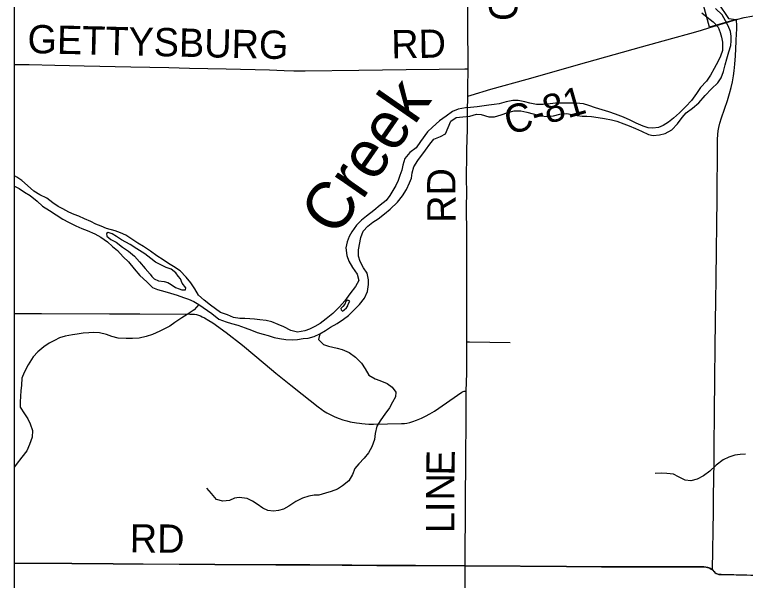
# Model space of a CAD drawing. Extents: x -87 to 2145, y -2128 to 440.
# Drawn here: x -21.62 to 17.09, y -1230.38 to -1200.4 of the extents above; entities that cross this region are included whole.
import ezdxf

# ---------------------------------------------------------------- set-up
doc = ezdxf.new("R2010")
doc.units = 0
for name, color, linetype in [('GM_X_Corporation', 7, 'Continuous'), ('GM_X_County_Road', 7, 'Continuous'), ('GM_X_County_Road_Text', 7, 'Continuous'), ('GM_X_Major_River', 7, 'Continuous'), ('GM_X_Major_River_Text', 7, 'Continuous'), ('GM_X_Minor_River', 7, 'Continuous'), ('GM_X_Township_Road', 7, 'Continuous'), ('GM_X_Township_Text', 7, 'Continuous'), ('SC_Scratch1', 7, 'Continuous')]:
    doc.layers.add(name, color=color, linetype=linetype)

msp = doc.modelspace()

# ---------------------------------------------------------------- linework, layer by layer
at = {"layer": 'GM_X_Corporation'}
msp.add_lwpolyline([(15.645, -1199.79), (16.19, -1200.598), (16.606, -1200.653), (15.194, -1201.071), (14.872, -1199.892)], dxfattribs=at)
at = {"layer": 'GM_X_County_Road'}
for points in [[(2.402, -1203.264), (2.402, -1203.242), (2.394, -1200.852), (2.388, -1199.683), (2.389, -1199.192), (2.393, -1198.818), (2.44, -1195.798), (2.472, -1192.879), (2.491, -1191.436), (2.497, -1190.304), (2.501, -1189.435), (2.507, -1188.271), (2.508, -1187.188), (2.497, -1185.974), (2.508, -1185.389)], [(15.2, -1201.085), (16.439, -1200.718), (16.612, -1200.667)], [(16.612, -1200.667), (17.033, -1200.553), (17.432, -1200.479), (18.193, -1200.365)], [(2.388, -1204.721), (2.564, -1204.668), (3.615, -1204.351), (5.525, -1203.815), (8.699, -1202.926), (11.586, -1202.107), (13.245, -1201.648), (14.144, -1201.396), (14.706, -1201.233), (15.2, -1201.085)], [(-21.617, -1203.042), (-20.84, -1203.048), (-19.479, -1203.078), (-17.937, -1203.113), (-15.461, -1203.173), (-13.444, -1203.208), (-12.361, -1203.229), (-10.409, -1203.267), (-8.114, -1203.327), (-7.344, -1203.353), (-6.82, -1203.373), (-6.229, -1203.382), (-3.392, -1203.337), (-0.882, -1203.316), (0.872, -1203.286), (2.233, -1203.266), (2.402, -1203.264)], [(2.388, -1204.721), (2.393, -1204.291), (2.402, -1203.264)], [(2.329, -1217.741), (2.332, -1215.445), (2.333, -1212.279), (2.325, -1210.355), (2.331, -1210.059), (2.325, -1208.847), (2.336, -1208.016), (2.342, -1207.571), (2.365, -1206.472), (2.378, -1205.52), (2.388, -1204.721)], [(2.308, -1220.351), (2.33, -1219.4), (2.329, -1217.741)], [(2.247, -1229.607), (2.267, -1226.169), (2.276, -1223.987), (2.303, -1221.806), (2.308, -1220.351)], [(-21.617, -1229.469), (-18.589, -1229.488), (-16.391, -1229.504), (-14.816, -1229.513), (-11.011, -1229.542), (-9.175, -1229.55), (-7.78, -1229.562), (-6.911, -1229.562), (-5.976, -1229.561), (-4.271, -1229.573), (-3.746, -1229.58), (-2.435, -1229.587), (-0.384, -1229.59), (2.247, -1229.607)], [(2.151, -1245.188), (2.161, -1243.21), (2.168, -1242.522), (2.182, -1240.75), (2.184, -1239.913), (2.187, -1239.274), (2.188, -1238.568), (2.189, -1237.716), (2.205, -1235.764), (2.219, -1233.549), (2.226, -1232.089), (2.241, -1230.4), (2.247, -1229.607)]]:
    msp.add_lwpolyline(points, dxfattribs=at)
at = {"layer": 'GM_X_Major_River'}
for points in [[(0.141, -1207.591), (0.377, -1207.274), (0.582, -1206.997), (0.935, -1206.853), (1.198, -1206.717), (1.354, -1206.389), (1.49, -1206.05), (1.774, -1205.855), (2.125, -1205.821), (2.486, -1205.776), (2.849, -1205.672), (3.099, -1205.687), (3.498, -1205.814), (3.809, -1205.819), (4.151, -1205.714), (4.514, -1205.58), (4.836, -1205.505), (5.187, -1205.501), (5.517, -1205.567), (5.856, -1205.663), (6.245, -1205.77), (6.605, -1205.806), (6.927, -1205.771), (7.259, -1205.676), (7.63, -1205.643), (8.06, -1205.73), (8.44, -1205.777), (8.691, -1205.781), (8.941, -1205.805), (9.291, -1205.851), (9.631, -1205.907), (9.99, -1205.983), (10.28, -1206.048), (10.648, -1206.185), (10.927, -1206.299), (11.266, -1206.435), (11.594, -1206.581), (11.952, -1206.758), (12.211, -1206.812), (12.543, -1206.778), (12.845, -1206.693), (13.189, -1206.498), (13.495, -1206.192), (13.741, -1205.856), (13.956, -1205.599), (14.28, -1205.364), (14.626, -1205.079), (14.963, -1204.684), (15.29, -1204.328), (15.626, -1204.013), (15.801, -1203.756), (15.936, -1203.417), (16.023, -1203.058), (16.108, -1202.749), (16.214, -1202.38), (16.31, -1202.041), (16.334, -1201.79), (16.339, -1201.54), (16.293, -1201.289), (16.177, -1200.986), (16.031, -1200.733), (15.856, -1200.419), (15.511, -1200.083)], [(14.786, -1200.301), (15.062, -1200.526), (15.379, -1200.782)], [(15.379, -1200.782), (15.655, -1201.067), (15.761, -1201.34), (15.817, -1201.591), (15.882, -1201.863), (15.885, -1202.294), (15.78, -1202.593), (15.655, -1202.871), (15.428, -1203.258), (15.242, -1203.606), (15.036, -1203.923), (14.72, -1204.259), (14.494, -1204.586), (14.227, -1204.952), (13.941, -1205.268), (13.605, -1205.603), (13.279, -1205.888), (13.025, -1206.104), (12.742, -1206.27), (12.489, -1206.386), (12.188, -1206.421), (11.938, -1206.397), (11.679, -1206.312), (11.311, -1206.146), (10.992, -1206), (10.634, -1205.833), (10.216, -1205.676), (9.857, -1205.55), (9.498, -1205.444), (9.159, -1205.338), (8.79, -1205.211), (8.511, -1205.136), (8.131, -1205.09), (7.79, -1205.084), (7.449, -1205.088), (7.028, -1205.101), (6.757, -1205.127), (6.376, -1205.16), (6.025, -1205.165), (5.665, -1205.088), (5.406, -1205.024), (5.046, -1204.958), (4.765, -1204.953), (4.423, -1205.027), (4.041, -1205.121), (3.79, -1205.157), (3.508, -1205.192), (3.127, -1205.256), (2.875, -1205.292), (2.534, -1205.326), (2.263, -1205.342), (1.881, -1205.416), (1.568, -1205.541), (1.234, -1205.775), (0.889, -1206.03), (0.512, -1206.365), (0.247, -1206.611)], [(0.247, -1206.611), (-0.122, -1207.128), (-0.349, -1207.454), (-0.684, -1207.708), (-0.951, -1208.023), (-1.048, -1208.381), (-1.113, -1208.65), (-1.208, -1208.918), (-1.294, -1209.197), (-1.429, -1209.464), (-1.584, -1209.721), (-1.749, -1209.978), (-1.935, -1210.245), (-2.26, -1210.499), (-2.586, -1210.782), (-2.982, -1211.085), (-3.237, -1211.29), (-3.502, -1211.565), (-3.759, -1211.91), (-3.904, -1212.167), (-4.01, -1212.446), (-4.076, -1212.764), (-4.024, -1213.166), (-3.919, -1213.458), (-3.725, -1213.802), (-3.482, -1214.157), (-3.388, -1214.489), (-3.565, -1214.816), (-3.863, -1215.2), (-4.13, -1215.565), (-4.407, -1215.89), (-4.754, -1216.244), (-5.11, -1216.517), (-5.425, -1216.771), (-5.708, -1216.925), (-5.991, -1217.07), (-6.253, -1217.155), (-6.625, -1217.227), (-6.984, -1217.14), (-7.351, -1216.943), (-7.659, -1216.827), (-7.997, -1216.69), (-8.295, -1216.604), (-8.635, -1216.568), (-8.905, -1216.542), (-9.165, -1216.517), (-9.415, -1216.512), (-9.695, -1216.497), (-10.015, -1216.46), (-10.342, -1216.314), (-10.71, -1216.186), (-10.977, -1215.991), (-11.234, -1215.806), (-11.579, -1215.539), (-11.884, -1215.263), (-12.068, -1214.939), (-12.282, -1214.615), (-12.527, -1214.31), (-12.851, -1213.983), (-13.197, -1213.746), (-13.464, -1213.591), (-13.741, -1213.395), (-14.077, -1213.178), (-14.412, -1212.932), (-14.798, -1212.684), (-15.095, -1212.518), (-15.352, -1212.343), (-15.728, -1212.085), (-16.016, -1211.97), (-16.284, -1211.864), (-16.742, -1211.735), (-17.04, -1211.609), (-17.309, -1211.504), (-17.586, -1211.358), (-17.914, -1211.222), (-18.212, -1211.086), (-18.47, -1210.991), (-18.739, -1210.875), (-19.056, -1210.699), (-19.313, -1210.564), (-19.59, -1210.368), (-19.916, -1210.132), (-20.273, -1209.945), (-20.599, -1209.748), (-20.934, -1209.451), (-21.239, -1209.195), (-21.496, -1209.02), (-21.617, -1208.945)], [(-21.617, -1209.487), (-21.378, -1209.623), (-21.101, -1209.808), (-20.794, -1209.985), (-20.419, -1210.292), (-20.134, -1210.548), (-19.768, -1210.775), (-19.422, -1211.002), (-19.066, -1211.239), (-18.769, -1211.395), (-18.382, -1211.593), (-18.054, -1211.739), (-17.776, -1211.835), (-17.369, -1212.023), (-17.052, -1212.199), (-16.706, -1212.436), (-16.44, -1212.682), (-16.174, -1212.907), (-15.87, -1213.233), (-15.585, -1213.509), (-15.292, -1213.875), (-14.978, -1214.221), (-14.614, -1214.569), (-14.32, -1214.865), (-14.041, -1214.97), (-13.663, -1215.078), (-13.354, -1215.164), (-13.006, -1215.271), (-12.668, -1215.398), (-12.399, -1215.483), (-12.121, -1215.608), (-11.863, -1215.754), (-11.172, -1216.248), (-10.807, -1216.535), (-10.409, -1216.673), (-10.121, -1216.768), (-9.802, -1216.865), (-9.404, -1216.993), (-9.076, -1217.129), (-8.778, -1217.245), (-8.46, -1217.341), (-8.19, -1217.397), (-7.862, -1217.503), (-7.593, -1217.569), (-7.244, -1217.626), (-6.903, -1217.642), (-6.633, -1217.618), (-6.331, -1217.573), (-6.071, -1217.549), (-5.758, -1217.455), (-5.445, -1217.321), (-5.142, -1217.147), (-4.888, -1216.971), (-4.534, -1216.768), (-4.189, -1216.545), (-3.935, -1216.34), (-3.68, -1216.105), (-3.343, -1215.761), (-3.086, -1215.426), (-2.919, -1215.079), (-2.872, -1214.709), (-2.867, -1214.459), (-2.95, -1214.097), (-3.135, -1213.814), (-3.319, -1213.48), (-3.404, -1213.208), (-3.397, -1212.868), (-3.284, -1212.21), (-3.158, -1211.882), (-2.912, -1211.607), (-2.638, -1211.402), (-2.354, -1211.217), (-2.029, -1210.963), (-1.723, -1210.709), (-1.336, -1210.337), (-1.069, -1210.012), (-0.852, -1209.676), (-0.705, -1209.318), (-0.6, -1209.06), (-0.565, -1208.781), (-0.479, -1208.472), (-0.252, -1208.136), (0.141, -1207.591)], [(-14.153, -1213.517), (-14.41, -1213.332), (-14.726, -1213.076), (-15.141, -1212.817), (-15.497, -1212.58), (-15.953, -1212.331), (-16.22, -1212.156), (-16.458, -1212.021), (-16.666, -1211.947), (-16.747, -1211.995), (-16.73, -1212.146), (-16.523, -1212.32), (-16.246, -1212.465), (-15.91, -1212.722), (-15.584, -1212.929), (-15.259, -1213.205), (-14.994, -1213.501), (-14.71, -1213.846), (-14.446, -1214.152), (-14.358, -1214.274)], [(-14.358, -1214.274), (-14.231, -1214.406), (-13.992, -1214.501), (-13.703, -1214.547), (-13.503, -1214.601), (-13.325, -1214.704), (-13.088, -1214.859), (-12.899, -1214.933), (-12.76, -1214.985), (-12.57, -1214.989), (-12.548, -1214.88), (-12.743, -1214.636), (-12.839, -1214.404), (-12.946, -1214.261), (-13.073, -1214.079), (-13.33, -1213.894), (-13.588, -1213.808), (-14.153, -1213.517)], [(-3.86, -1215.581), (-3.959, -1215.529), (-4.071, -1215.607), (-4.133, -1215.745), (-4.226, -1215.864), (-4.338, -1215.971), (-4.329, -1216.042), (-4.251, -1216.113)], [(-4.251, -1216.113), (-4.159, -1216.045), (-4.047, -1215.937), (-3.975, -1215.829), (-3.943, -1215.749), (-3.86, -1215.581)]]:
    msp.add_lwpolyline(points, dxfattribs=at)
at = {"layer": 'GM_X_Minor_River'}
for points in [[(-11.863, -1215.754), (-12.099, -1216.039), (-12.485, -1216.292), (-12.768, -1216.466), (-13.124, -1216.709), (-13.398, -1216.904), (-13.651, -1217.039), (-13.923, -1217.174), (-14.317, -1217.346), (-14.65, -1217.46), (-15.022, -1217.543), (-15.373, -1217.566), (-15.713, -1217.569), (-16.134, -1217.551), (-16.462, -1217.454), (-16.75, -1217.349), (-17.129, -1217.261), (-17.44, -1217.255), (-17.69, -1217.26), (-17.981, -1217.285), (-18.302, -1217.338), (-18.553, -1217.363), (-18.935, -1217.436), (-19.247, -1217.53), (-19.51, -1217.675), (-19.793, -1217.819), (-20.077, -1218.004), (-20.393, -1218.278), (-20.638, -1218.533), (-20.897, -1218.959), (-21.115, -1219.365), (-21.231, -1219.662), (-21.248, -1220.042), (-21.284, -1220.332), (-21.299, -1220.622), (-21.325, -1220.931), (-21.33, -1221.202), (-21.097, -1221.556), (-20.922, -1221.82), (-20.787, -1222.093), (-20.664, -1222.446), (-20.68, -1222.795), (-20.828, -1223.183), (-20.965, -1223.52), (-21.231, -1223.845), (-21.529, -1224.25), (-21.617, -1224.369)], [(-5.445, -1217.321), (-5.521, -1217.619), (-5.256, -1217.885), (-4.987, -1217.97), (-4.539, -1218.069), (-4.27, -1218.154), (-3.902, -1218.302), (-3.567, -1218.548), (-3.242, -1218.875), (-3.048, -1219.179), (-2.854, -1219.513), (-2.528, -1219.71), (-2.269, -1219.785), (-1.891, -1219.942), (-1.615, -1220.148), (-1.42, -1220.402), (-1.435, -1220.662), (-1.6, -1220.939), (-1.766, -1221.246), (-2.013, -1221.571), (-2.219, -1221.867), (-2.436, -1222.213), (-2.513, -1222.592), (-2.559, -1222.921), (-2.697, -1223.299), (-2.873, -1223.626), (-3.099, -1223.901), (-3.385, -1224.206), (-3.59, -1224.462), (-3.717, -1224.78), (-3.913, -1225.106), (-4.249, -1225.38), (-4.513, -1225.555), (-4.845, -1225.678), (-5.147, -1225.762), (-5.5, -1225.866), (-5.75, -1225.871), (-6.042, -1225.925), (-6.374, -1226.029), (-6.718, -1226.212), (-7.093, -1226.455), (-7.367, -1226.609), (-7.638, -1226.674), (-7.909, -1226.709), (-8.209, -1226.673), (-8.467, -1226.548), (-8.763, -1226.342), (-9.02, -1226.177), (-9.298, -1226.041), (-9.728, -1225.983), (-9.979, -1226.028), (-10.241, -1226.143), (-10.583, -1226.186), (-10.921, -1226.089), (-11.195, -1225.774), (-11.43, -1225.499)], [(17.092, -1223.692), (16.811, -1223.707), (16.53, -1223.743), (16.207, -1223.857), (15.914, -1223.993), (15.539, -1224.277), (15.213, -1224.602), (14.878, -1224.847), (14.544, -1225.022), (14.192, -1225.116), (13.902, -1225.071), (13.554, -1224.895), (13.276, -1224.76), (12.935, -1224.714), (12.665, -1224.7), (12.314, -1224.724)]]:
    msp.add_lwpolyline(points, dxfattribs=at)
at = {"layer": 'GM_X_Township_Road'}
for points in [[(15.354, -1229.831), (15.398, -1226.715), (15.405, -1225.912), (15.428, -1224.109), (15.444, -1222.846), (15.457, -1221.961), (15.461, -1221.436), (15.478, -1219.764), (15.488, -1217.96), (15.521, -1215.5), (15.534, -1214.467), (15.562, -1212.827), (15.572, -1211.597), (15.592, -1210.089), (15.608, -1207.401), (15.613, -1207.023), (15.63, -1206.745), (15.649, -1206.566), (15.683, -1206.375), (15.739, -1206.153), (15.825, -1205.87), (16.134, -1204.953), (16.249, -1204.576), (16.335, -1204.26), (16.404, -1203.957), (16.458, -1203.651), (16.496, -1203.375), (16.529, -1203.017), (16.563, -1202.576), (16.584, -1202.216), (16.601, -1201.806), (16.622, -1201.385), (16.629, -1201.2), (16.631, -1201.107), (16.63, -1201.003), (16.612, -1200.667)], [(-21.617, -1216.241), (-20.192, -1216.246), (-16.583, -1216.252), (-14.992, -1216.253), (-12.334, -1216.268), (-12.203, -1216.272), (-12.086, -1216.281), (-11.991, -1216.296), (-11.88, -1216.324), (-11.773, -1216.365), (-11.676, -1216.411), (-11.568, -1216.468), (-11.337, -1216.605), (-11.121, -1216.742), (-10.414, -1217.252), (-9.547, -1217.911), (-8.343, -1218.925), (-7.773, -1219.394), (-6.981, -1220.032), (-6.379, -1220.513), (-5.535, -1221.192), (-5.351, -1221.329), (-5.254, -1221.395), (-5.173, -1221.446), (-5.074, -1221.504), (-4.982, -1221.555), (-4.872, -1221.612), (-4.648, -1221.716), (-4.42, -1221.808), (-4.234, -1221.871), (-4.013, -1221.933), (-3.837, -1221.973), (-3.514, -1222.032), (-3.358, -1222.057), (-3.222, -1222.074), (-3.043, -1222.091), (-2.863, -1222.098), (-2.6, -1222.098), (-1.125, -1222.077), (-0.961, -1222.068), (-0.847, -1222.053), (-0.688, -1222.016), (-0.53, -1221.97), (-0.33, -1221.897), (-0.073, -1221.787), (0.148, -1221.681), (0.379, -1221.556), (0.617, -1221.41), (2.078, -1220.412), (2.146, -1220.374), (2.2, -1220.357), (2.253, -1220.351), (2.308, -1220.351)], [(2.329, -1217.741), (2.479, -1217.74), (4.623, -1217.777)], [(2.247, -1229.607), (5.174, -1229.628), (7.618, -1229.651), (9.471, -1229.665), (13.901, -1229.659), (14.574, -1229.66), (14.736, -1229.662), (14.902, -1229.669), (15.007, -1229.678), (15.087, -1229.693), (15.148, -1229.711), (15.215, -1229.741), (15.283, -1229.783), (15.354, -1229.831)], [(15.354, -1229.831), (15.438, -1229.934), (15.484, -1229.978), (15.539, -1230.014), (15.608, -1230.044), (15.682, -1230.065), (15.757, -1230.073), (15.816, -1230.075), (21.244, -1230.203)]]:
    msp.add_lwpolyline(points, dxfattribs=at)
at = {"layer": 'GM_X_Township_Text'}
msp.add_lwpolyline([(-21.617, -1229.455), (-18.595, -1229.474), (-16.397, -1229.49), (-14.822, -1229.499), (-11.017, -1229.528), (-9.181, -1229.536), (-7.787, -1229.548), (-6.917, -1229.548), (-5.983, -1229.547), (-4.277, -1229.559), (-3.752, -1229.565), (-2.441, -1229.573), (-0.391, -1229.576), (2.241, -1229.593), (5.167, -1229.614), (7.612, -1229.637), (9.465, -1229.651), (13.894, -1229.645), (14.568, -1229.646), (14.73, -1229.648), (14.896, -1229.654), (15.001, -1229.664), (15.081, -1229.679), (15.142, -1229.696), (15.209, -1229.727), (15.277, -1229.769), (15.348, -1229.817), (15.432, -1229.919), (15.478, -1229.963), (15.533, -1230), (15.602, -1230.03), (15.676, -1230.051), (15.75, -1230.059), (15.809, -1230.061), (21.238, -1230.188)], dxfattribs=at)
at = {"layer": 'SC_Scratch1'}
msp.add_lwpolyline([(-21.617, -825.188), (230.183, -825.188), (230.183, -1245.188), (-21.617, -1245.188)], close=True, dxfattribs=at)

# ---------------------------------------------------------------- texts
at = {"layer": 'GM_X_County_Road_Text'}
for s, rotation, p in [('C-9', 89.5607, (5.009, -1200.742)), ('GETTYSBURG', 358.6485, (-20.948, -1202.436)), ('RD', 0.9872, (-1.656, -1202.723)), ('C-81', 15.9447, (4.57, -1206.787)), ('RD', 90.4996, (1.747, -1211.426)), ('E', 89.0335, (1.681, -1224.836)), ('N', 89.9763, (1.681, -1226.149)), ('I', 90, (1.681, -1226.765)), ('L', 90, (1.681, -1227.887)), ('RD', 359.5064, (-15.522, -1228.903))]:
    msp.add_text(s, height=1.5, rotation=rotation, dxfattribs=at).set_placement(p)
at = {"layer": 'GM_X_Major_River_Text'}
msp.add_text('Creek', height=2.4993, rotation=55.2062, dxfattribs=at).set_placement((-4.581, -1212.251))

doc.saveas('drawing.dxf')
